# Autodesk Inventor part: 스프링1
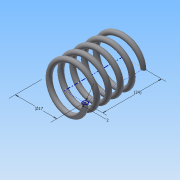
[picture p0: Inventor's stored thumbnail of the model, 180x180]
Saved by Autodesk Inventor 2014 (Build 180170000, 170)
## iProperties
Created: 2016-01
Part Number: 스프링1
Material: 강철, 탄소
Document SubType Name: Modeling
Designer: Administrator
Density: 7.87 g/cm^3
Appearance: 반연마
Mass: 6.46883 g
Surface Area: 16.7185 cm^2
Volume: 0.821961 cm^3
Author: Administrator
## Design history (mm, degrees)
sketch "스케치1"
  geometry: L1 (0, 0)-(8.5, 0); L2 (8.5, 0)-(8.5, 20.5); L3 (8.5, 20.5)-(0, 20.5); L4 (0, 20.5)-(0, 0); C1 r 1 at (8.5, 0)
  constraints: 8 end point, 2 parallel, 1 centre point, 1 coincident, 1 horizontal, 1 perpendicular
  dimensions: "d0" = 20.5 distance of L1.end L2.end (derived); "d1" = 2 diameter of C1; "d2" = 17 diameter of L2 L4
feature "코일1" sketch "스케치1" pitch "d3" = 10; turns "d5" = 5; dims "d4" = 20.5 (= d0), "d6" = 0, angle "d7" = 90 deg, angle "d8" = 90 deg, "d9" = 0, "d10" = 0
node "작업 평면1"
sketch "스케치2"
  geometry: L1 (7.5, 0)-(9.5, 0) reference; 1 further point
  constraints: 1 horizontal alignment
extrude "돌출1" cut sketch "스케치2" distance "d12" = 10; taper "d13" = 0 deg
node "작업 평면2"
sketch "스케치3"
  geometry: L1 (-7.5, 0)-(-9.5, 0) reference; 1 further point
  constraints: 1 horizontal alignment
extrude "돌출2" cut sketch "스케치3" distance "d15" = 10; taper "d16" = 0 deg
node "솔리드1"
node "절단 모서리 투영1"
node "절단 모서리 투영2"
other parameters: "d11" = 0, "d14" = -20.5 (= -d0)
